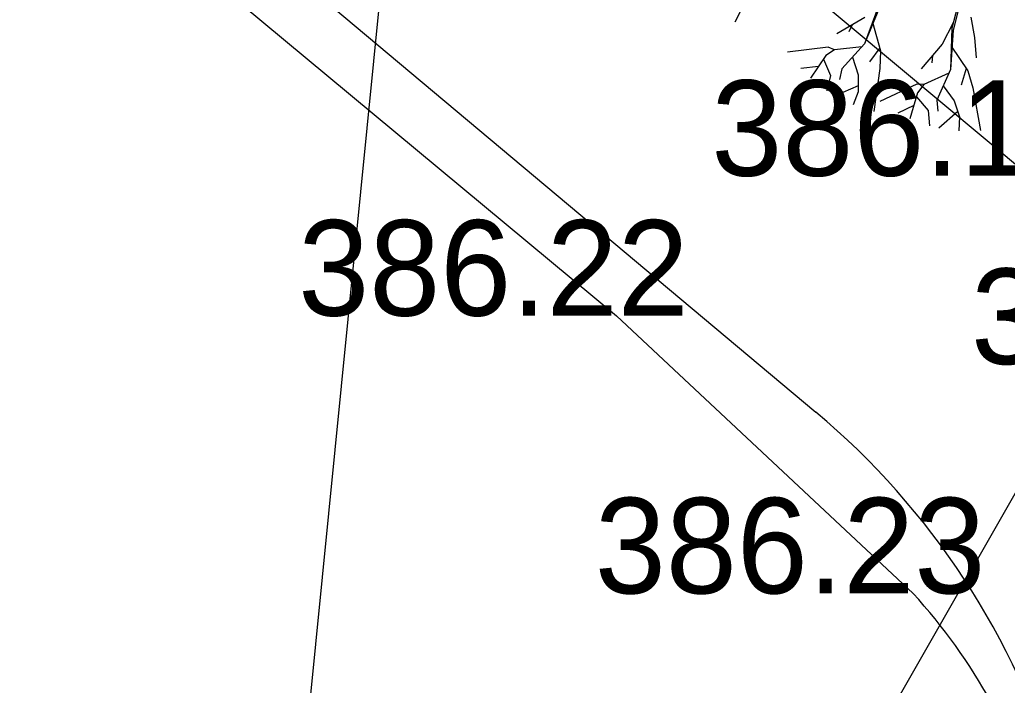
# Model space of a CAD drawing. Extents: x -438233 to -437334, y -1133133 to -1132623.
# Drawn here: x -438149.26 to -438141.5, y -1132967.72 to -1132962.49 of the extents above; entities that cross this region are included whole.
import ezdxf

# ---------------------------------------------------------------- set-up
doc = ezdxf.new("R2010")
doc.units = 0
for name, color, linetype in [('Vrstva 1', 7, 'Continuous'), ('Vrstva 11', 7, 'Continuous'), ('Vrstva 3', 7, 'Continuous'), ('Vrstva 40', 7, 'Continuous'), ('Vrstva 53', 7, 'Continuous')]:
    doc.layers.add(name, color=color, linetype=linetype)

msp = doc.modelspace()

# ---------------------------------------------------------------- linework, layer by layer
at = {"layer": 'Vrstva 1'}
for p, q in [((-438152.337, -1132957.7578), (-438143.0069, -1132965.5742)), ((-438143.4589, -1132962.1474), (-438143.643, -1132962.5126)), ((-438141.8833, -1132962.3369), (-438141.9403, -1132962.5594)), ((-438141.8659, -1132962.3243), (-438141.9301, -1132962.5756)), ((-438142.5137, -1132962.3789), (-438142.6246, -1132962.6824)), ((-438142.5089, -1132962.3969), (-438142.6246, -1132962.6824)), ((-438142.624, -1132962.4748), (-438142.8418, -1132962.6044)), ((-438142.5623, -1132962.5114), (-438142.4999, -1132962.7363)), ((-438141.9295, -1132962.518), (-438142.0147, -1132962.686)), ((-438141.791, -1132962.473), (-438141.761, -1132962.6326)), ((-438142.7236, -1132962.5336), (-438142.7476, -1132962.5876)), ((-438141.9403, -1132962.5594), (-438141.9505, -1132962.8827)), ((-438141.9301, -1132962.5756), (-438141.9505, -1132962.8827)), ((-438141.761, -1132962.6326), (-438141.7484, -1132962.7915)), ((-438142.9119, -1132962.7087), (-438143.2292, -1132962.7471)), ((-438142.8603, -1132962.7285), (-438142.9287, -1132962.7747)), ((-438142.8603, -1132962.7285), (-438142.9119, -1132962.7087)), ((-438142.6462, -1132962.7051), (-438142.8603, -1132962.7285)), ((-438142.6246, -1132962.6824), (-438142.8028, -1132962.8779)), ((-438142.5059, -1132962.7141), (-438142.5851, -1132962.8245)), ((-438142.4999, -1132962.7363), (-438142.5047, -1132962.8755)), ((-438142.0147, -1132962.686), (-438142.1808, -1132962.8773)), ((-438141.9445, -1132962.701), (-438141.8144, -1132962.8953)), ((-438142.9287, -1132962.7747), (-438143.0505, -1132962.9505)), ((-438142.9467, -1132962.8035), (-438142.8939, -1132962.9319)), ((-438142.72, -1132962.7867), (-438142.6756, -1132962.9265)), ((-438142.0903, -1132962.7735), (-438142.0957, -1132962.8323)), ((-438142.9881, -1132962.8599), (-438143.1248, -1132962.8767)), ((-438142.8028, -1132962.8779), (-438142.8214, -1132962.9624)), ((-438142.5047, -1132962.8755), (-438142.5527, -1132963.2131)), ((-438141.9505, -1132962.8827), (-438142.0573, -1132963.125)), ((-438141.8276, -1132962.8755), (-438141.8671, -1132963.0056)), ((-438141.8144, -1132962.8953), (-438141.7754, -1132963.0278)), ((-438142.8939, -1132962.9319), (-438142.9203, -1132963.0512)), ((-438142.6756, -1132962.9265), (-438142.6744, -1132963.0578)), ((-438141.9631, -1132962.9115), (-438142.1592, -1132963.0014)), ((-438142.6744, -1132963.0128), (-438142.8573, -1132963.0908)), ((-438142.6744, -1132963.0578), (-438142.7158, -1132963.1598)), ((-438142.2138, -1132962.999), (-438142.5041, -1132963.1358)), ((-438142.1592, -1132963.0014), (-438142.2138, -1132962.999)), ((-438142.1592, -1132963.0014), (-438142.209, -1132963.0668)), ((-438142.0075, -1132963.0128), (-438141.9211, -1132963.1304)), ((-438141.7754, -1132963.0278), (-438141.7142, -1132963.3637)), ((-438142.209, -1132963.0668), (-438142.2696, -1132963.2713)), ((-438142.2168, -1132963.0992), (-438142.1268, -1132963.2053)), ((-438142.0573, -1132963.125), (-438142.0483, -1132963.2113)), ((-438141.9211, -1132963.1304), (-438141.8791, -1132963.2545)), ((-438142.2384, -1132963.1664), (-438142.3631, -1132963.2257)), ((-438142.1268, -1132963.2053), (-438142.1142, -1132963.3259)), ((-438141.8935, -1132963.2125), (-438142.0417, -1132963.3433)), ((-438141.8791, -1132963.2545), (-438141.8851, -1132963.3649)), ((-438144.574, -1132964.816), (-438144.574, -1132964.816)), ((-438142.244, -1132966.996), (-438142.244, -1132966.996))]:
    msp.add_line(p, q, dxfattribs=at)
msp.add_arc((-438146.86, -1132970.1735), 6, 16.44565, 50.04476, dxfattribs=at)
at = {"layer": 'Vrstva 11'}
for points in [[(-438153.362, -1132953.683), (-438141.329, -1132963.718), (-438139.289, -1132965.196)], [(-438149.747, -1132960.758), (-438149.622, -1132960.625), (-438144.574, -1132964.816), (-438142.244, -1132966.996)]]:
    msp.add_lwpolyline(points, dxfattribs=at)
msp.add_arc((-438145.6136, -1132970.0676), 4.5595, 15.82768, 42.3507, dxfattribs=at)
at = {"layer": 'Vrstva 40'}
msp.add_line((-438145.8813, -1132956.7849), (-438150.6122, -1133004.3095), dxfattribs=at)
at = {"layer": 'Vrstva 53'}
msp.add_lwpolyline([(-438111.68, -1133002.95), (-438112.12, -1133002.5), (-438122.55, -1132995.83), (-438124.94, -1132993.34), (-438127.48, -1132990.73), (-438128.12, -1132989.43), (-438134.1, -1132984.54), (-438140.26, -1132979.82), (-438141.19, -1132978.73), (-438141.97, -1132973.72), (-438142.51, -1132968.08), (-438140.08, -1132963.83), (-438137.6, -1132962.74), (-438135.49, -1132962.32), (-438133.71, -1132961.01), (-438132.67, -1132959.55), (-438131.52, -1132960.06), (-438130.71, -1132960.47)], dxfattribs=at)

# ---------------------------------------------------------------- texts
at = {"layer": 'Vrstva 3'}
for s, p in [('386.19 ', (-438143.829, -1132963.718)), ('386.22 ', (-438147.074, -1132964.816)), ('386.16 ', (-438141.789, -1132965.196)), ('386.23 ', (-438144.744, -1132966.996))]:
    msp.add_text(s, height=0.75, dxfattribs=at).set_placement(p)

doc.saveas('drawing.dxf')
